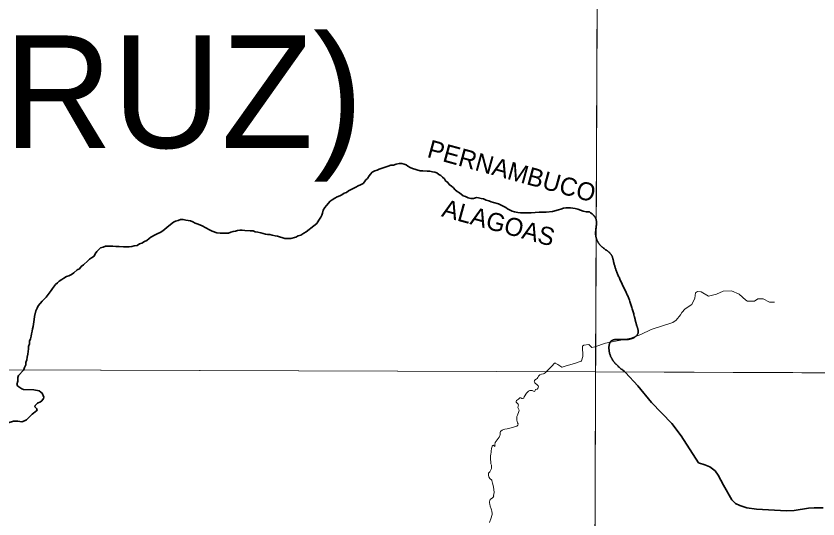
# Model space of a CAD drawing. Extents: x -1643653 to 4543381, y 1624270 to 13878484.
# Drawn here: x 594066 to 597627, y 8920336 to 8922571 of the extents above; entities that cross this region are included whole.
import ezdxf
from ezdxf.enums import TextEntityAlignment as Align

# ---------------------------------------------------------------- set-up
doc = ezdxf.new("R2010")
doc.units = 0
doc.header["$LTSCALE"] = 200
doc.linetypes.add('LONG_DASH_SHORT_DASH', pattern=[9.9, 6, -1.2, 1.5, -1.2])
doc.layers.add('6', color=7, linetype='Continuous', lineweight=13)
doc.layers.add('60', color=7, linetype='Continuous', lineweight=13)

msp = doc.modelspace()

# ---------------------------------------------------------------- linework, layer by layer
at = {"layer": '6'}
for points in [[(585656.3, 8924738.8), (596655.5, 8924715.8), (596639.8, 8920989.8), (585645.8, 8921027.3)], [(607600.8, 8920952.4), (596639.8, 8920989.8), (596608.8, 8909934.4), (607569.8, 8909894.9)]]:
    msp.add_lwpolyline(points, close=True, dxfattribs=at)
for points in [[(596655.5, 8924715.8), (596593.3, 8909930.3), (596531.7, 8896026.7)], [(597434.3, 8921299.7), (597411.5, 8921299.7), (597383.8, 8921313.7), (597360.5, 8921314.5), (597345.6, 8921303.6), (597314.4, 8921304.1), (597306.5, 8921308), (597277.6, 8921334.7), (597243.3, 8921349.7), (597206.9, 8921347.9), (597176.8, 8921335.1), (597140.6, 8921326.9), (597109.4, 8921345.3), (597091.8, 8921347), (597084, 8921340.9), (597080.4, 8921317.9), (597067.7, 8921289.1), (597038.2, 8921270.1), (597022.5, 8921254), (597017.6, 8921243.4), (596998.4, 8921219.3), (596982.5, 8921209.2), (596886.2, 8921177.5), (596841.4, 8921155.3), (596796, 8921139.4), (596684.4, 8921117.9), (596636.5, 8921101.1), (596623.7, 8921097.9), (596609.9, 8921111.7), (596587.7, 8921108.9), (596581.2, 8921103.5)], [(596581.2, 8921103.5), (596583.4, 8921058), (596577.4, 8921038.4), (596576.5, 8921036.9), (596546.9, 8921026.8), (596509.1, 8921016.7), (596491.7, 8921010.3), (596490, 8921010.8), (596472.1, 8921022.3), (596460.7, 8921029.2), (596459.6, 8921029.6), (596457.7, 8921028), (596445.2, 8921015.4), (596419.5, 8920988.9)], [(574684.9, 8921064.7), (596639.8, 8920989.8), (607636.3, 8920937.2), (626625.7, 8920820.5)], [(596419.5, 8920988.9), (596416.1, 8920985.5), (596411.6, 8920983.1), (596407.8, 8920981.7), (596399.5, 8920980), (596392.7, 8920976.5), (596389.8, 8920974.2), (596389.4, 8920973.2), (596388.5, 8920972.8), (596388, 8920971.8), (596387, 8920970.8), (596385.5, 8920968), (596383.2, 8920964.5), (596380.2, 8920960.7), (596376.2, 8920958.1), (596372.5, 8920956.2), (596369.6, 8920953.6), (596368.4, 8920952), (596367.4, 8920948.3), (596368.1, 8920946.1), (596368.2, 8920944.4), (596370, 8920941.5), (596371.9, 8920939.1), (596374.2, 8920937.3), (596377.3, 8920934.5), (596381, 8920931.9), (596384.8, 8920927.5), (596384.8, 8920927.5), (596385.6, 8920924.6), (596383.9, 8920916.4), (596383.6, 8920915.6), (596379.7, 8920913.5), (596373.2, 8920911.8), (596371.3, 8920906.5), (596370.2, 8920904.4), (596367.6, 8920903.1), (596364.1, 8920903.5), (596358.3, 8920907.2), (596357.3, 8920907.5), (596352.8, 8920907.7), (596347.5, 8920907.1), (596342.6, 8920904.7), (596337.1, 8920900), (596333.1, 8920895.9), (596322.9, 8920878.2)], [(596322.9, 8920878.2), (596321.8, 8920875.5), (596320.5, 8920873.2), (596315.8, 8920871.4), (596312.6, 8920871.3), (596310.4, 8920872.7), (596308.4, 8920874.5), (596303, 8920874.9), (596298.1, 8920868.6), (596293.7, 8920866.1), (596288.5, 8920862.6), (596287.3, 8920858.1), (596287.3, 8920855.8), (596289.2, 8920853.1), (596295.7, 8920846.8), (596296.2, 8920845.8), (596296.8, 8920842.9), (596295, 8920832), (596300.2, 8920819.4), (596299.3, 8920813.8), (596292.4, 8920797.3), (596290.7, 8920791.7), (596289.4, 8920786.3), (596290.7, 8920775), (596292.3, 8920769.4), (596293.4, 8920763.9), (596295.3, 8920758.3), (596294.3, 8920752.9), (596293.5, 8920751), (596289.7, 8920748.2), (596275.6, 8920744), (596269.9, 8920743.1), (596264.5, 8920741.9), (596258.8, 8920739.7), (596253.2, 8920738.4), (596247.6, 8920736.7), (596236.5, 8920735.2), (596230.9, 8920733.7), (596225.4, 8920731.3), (596218.8, 8920726.5), (596218.2, 8920725.5), (596216.7, 8920722.2), (596215.8, 8920715.7), (596215.7, 8920710.1), (596215.3, 8920707.1), (596211.6, 8920699.2), (596197.7, 8920682), (596193.8, 8920675.4), (596193.1, 8920667.7), (596194.2, 8920664.1), (596192.8, 8920660.7), (596192.2, 8920658.1), (596192, 8920658), (596185.8, 8920663.5), (596183.3, 8920663.3), (596181.1, 8920659.8), (596179.3, 8920654.3), (596178.1, 8920648.7), (596176.8, 8920637.8), (596175.7, 8920632), (596175.2, 8920626.1), (596173.4, 8920615.3), (596172.7, 8920609.8), (596172.8, 8920603.6), (596174.4, 8920586.9), (596175.3, 8920581.1), (596177.2, 8920575.1), (596177.8, 8920569.5), (596177.6, 8920563.3), (596177.3, 8920560), (596173.2, 8920551.4), (596169.7, 8920546), (596164.5, 8920539), (596163.8, 8920534.7), (596164.4, 8920529.3), (596165.8, 8920523.5), (596169.8, 8920515.6), (596179, 8920508.3), (596179.7, 8920507.3), (596181.2, 8920501.9), (596182.2, 8920495.7), (596184.6, 8920484.3), (596186.5, 8920477.5), (596189.9, 8920455.4)], [(596189.9, 8920455.4), (596189.5, 8920454.3), (596187.2, 8920440.2), (596187.2, 8920439.4), (596188.3, 8920437.7), (596188.3, 8920437.1), (596185.5, 8920433.8), (596181.5, 8920430.2), (596172.4, 8920423), (596169.5, 8920418.8), (596168.2, 8920412.8), (596168.7, 8920407.7), (596169.5, 8920402.7), (596172, 8920392.7), (596176.5, 8920381.4), (596178, 8920376.9), (596179.2, 8920371.6), (596180.6, 8920361.1), (596180.6, 8920356.3), (596179.6, 8920351.4), (596176.7, 8920340.8), (596168, 8920320.1)]]:
    msp.add_lwpolyline(points, dxfattribs=at)
at = {"layer": '6', "linetype": 'LONG_DASH_SHORT_DASH', "lineweight": 35}
for points in [[(595503.7, 8921771.9), (595513.3, 8921776.4), (595523.8, 8921783.5), (595533.3, 8921787.6), (595542.8, 8921794.6), (595554.8, 8921799.7), (595565.9, 8921806.8), (595575.4, 8921810.3), (595584.9, 8921816.9), (595595.4, 8921821), (595607, 8921827), (595613.5, 8921834.6), (595619.5, 8921842.7), (595626.5, 8921849.7), (595635, 8921860.3), (595640.5, 8921868.3), (595647.9, 8921877.9), (595660, 8921882.5), (595669.5, 8921886.5), (595678, 8921891.1), (595709.1, 8921900.8), (595718.1, 8921904.3), (595730.2, 8921907.9), (595742.2, 8921908.9), (595753.8, 8921913), (595767.3, 8921916.1), (595779.9, 8921915.6), (595789.4, 8921912.7), (595799, 8921909.2), (595806.5, 8921903.2), (595816.6, 8921897.7), (595827.1, 8921893.8), (595861.3, 8921882.9), (595871.9, 8921882.9), (595892.5, 8921882), (595904, 8921881.1), (595916.1, 8921878.1), (595925.6, 8921877.1), (595934.7, 8921873.7), (595943.7, 8921867.2), (595952.3, 8921861.7), (595960.3, 8921855.2), (595968.4, 8921847.7), (595974, 8921838.7), (595983.5, 8921831.2), (595990.1, 8921821.7), (596000.2, 8921815.7), (596007.7, 8921809.2), (596016.8, 8921798.7), (596024.9, 8921790.7), (596035.4, 8921784.8), (596052.1, 8921771.8), (596061.6, 8921768.8), (596073.7, 8921763.3), (596085.2, 8921760.4), (596097.3, 8921760.4), (596110.3, 8921764.5), (596119.9, 8921763.6), (596131.4, 8921760.1), (596142.5, 8921759.1), (596153.6, 8921753.2), (596165.6, 8921749.7), (596176.7, 8921745.2), (596186.7, 8921741.8), (596208.8, 8921735.8), (596232, 8921724.4), (596241.6, 8921720.9), (596249.1, 8921714.9), (596268.7, 8921704.5), (596279.8, 8921701), (596294.3, 8921698.1), (596306.9, 8921697.1), (596320, 8921696.7), (596353.6, 8921696.8), (596389.2, 8921699), (596420.4, 8921700.1), (596448.5, 8921702.3), (596474.6, 8921709.4), (596486.1, 8921713.5), (596497.6, 8921717), (596508.2, 8921718.1), (596528.7, 8921718.2), (596538.8, 8921717.7), (596549.8, 8921716.3), (596560.4, 8921712.3), (596572.5, 8921708.8), (596585, 8921703.4), (596598.6, 8921701.4), (596611.6, 8921701.5)], [(594412.5, 8921504.4), (594417, 8921514), (594424.5, 8921525.1), (594441.5, 8921540.7), (594453.5, 8921543.8), (594464, 8921547.8), (594495.2, 8921548), (594509.2, 8921547.5), (594523.3, 8921547.6), (594543.9, 8921545.7), (594569, 8921545.8), (594580.6, 8921546.3), (594590.1, 8921549.9), (594603.7, 8921551.5), (594614.2, 8921558.1), (594625.2, 8921562.1), (594636.2, 8921569.7), (594646.8, 8921574.3), (594657.3, 8921581.8), (594664.3, 8921588.9), (594683.8, 8921599), (594696.4, 8921604.1), (594705.9, 8921609.2), (594718.4, 8921616.8), (594744.4, 8921639), (594765, 8921654.6), (594774, 8921659.2), (594786.5, 8921662.7), (594796.6, 8921666.8), (594808.1, 8921666.8), (594820.7, 8921664.4), (594841.3, 8921661.5), (594851.3, 8921657), (594860.9, 8921651), (594870.5, 8921647.1), (594883, 8921642.6), (594893.1, 8921638.6), (594925.8, 8921621.2), (594936.4, 8921614.7), (594958, 8921608.3), (594972.1, 8921605.8), (594986.1, 8921605.9), (594998.2, 8921606.4), (595010.2, 8921606.5), (595019.3, 8921610.1), (595029.8, 8921613.6), (595040.8, 8921614.7), (595049.9, 8921618.2), (595059.9, 8921618.8), (595070, 8921618.8), (595081.5, 8921618.4), (595106.1, 8921616.5), (595118.7, 8921616), (595128.2, 8921612.6), (595140.3, 8921610.1), (595153.9, 8921608.2), (595162.9, 8921604.7), (595173.5, 8921601.7), (595183, 8921600.8), (595193.1, 8921600.3), (595203.6, 8921596.8), (595217.2, 8921593.9), (595226.7, 8921592.9), (595259.9, 8921582), (595287, 8921582.1), (595309.1, 8921588.3), (595319.1, 8921594.3), (595331.2, 8921597.9), (595343.7, 8921605.5), (595354.2, 8921612.6), (595388.8, 8921638.3), (595402.3, 8921649.4), (595410.8, 8921664.5), (595419.2, 8921676.6), (595423.7, 8921686.2), (595427.2, 8921695.2), (595430.2, 8921707.8), (595437.2, 8921719.8), (595444.2, 8921729.4), (595460.7, 8921748.6), (595469.7, 8921754.1), (595481.2, 8921762.2), (595491.7, 8921767.8), (595503.7, 8921771.9)], [(594099.8, 8920996.9), (594100.5, 8921000.4), (594104, 8921009.5), (594109.4, 8921021.6), (594109.9, 8921032.1), (594113.9, 8921042.7), (594114.8, 8921055.2), (594118.3, 8921067.8), (594119.8, 8921079.9), (594121.7, 8921092.4), (594121.7, 8921102.5), (594125.7, 8921114.5), (594126.1, 8921125.6), (594130.1, 8921136.6), (594133.6, 8921148.2), (594134.5, 8921159.3), (594138, 8921170.8), (594138.5, 8921180.4), (594142.4, 8921191.4), (594146.8, 8921222.6), (594147.8, 8921236.1), (594153.7, 8921261.3), (594160.2, 8921273.3), (594164.2, 8921283.4), (594181.7, 8921304.6), (594199.2, 8921321.7), (594213.7, 8921339.4), (594222.2, 8921350.9), (594228.2, 8921360.5), (594241.7, 8921377.7), (594249.7, 8921386.2), (594257.7, 8921393.3), (594269.2, 8921400.9), (594278.7, 8921405.9), (594289.8, 8921413), (594300.8, 8921417.1), (594311.8, 8921422.1), (594322.3, 8921429.7), (594337.9, 8921443.3), (594348.4, 8921448.4), (594354.9, 8921457.5), (594365.9, 8921466.1), (594384.9, 8921482.7), (594392.4, 8921491.3), (594401.5, 8921496.3), (594412.5, 8921504.4)], [(594176.2, 8920899.4), (594168.7, 8920905.5), (594145.6, 8920910), (594098.9, 8920911.9), (594091.7, 8920913.9), (594073.9, 8920925.8), (594070.1, 8920934.3), (594074.3, 8920949.1), (594073.3, 8920964.4), (594077, 8920974.4), (594099.8, 8920996.9)], [(596772.7, 8920987.6), (596827.2, 8920927.7), (596887.6, 8920854.4), (596978.3, 8920759.7), (597020.1, 8920705.3), (597096.6, 8920585), (597125.2, 8920577.1), (597146.5, 8920568.5), (597170.2, 8920550.2), (597184.9, 8920530.7), (597208.4, 8920486.7), (597244.6, 8920421.2), (597260.6, 8920405.6), (597280.5, 8920395.7), (597310.8, 8920386.4), (597353.9, 8920380.3), (597487.5, 8920372), (597521, 8920374.3), (597585, 8920384.1), (597610.2, 8920386.4), (597650.2, 8920385.4)], [(594030.9, 8920764), (594054.9, 8920770.3), (594073.9, 8920770.6), (594092, 8920768.1), (594103, 8920771.6), (594111.8, 8920776.3), (594138.2, 8920802.2), (594156.9, 8920817.3), (594159.3, 8920821.2), (594159, 8920825), (594150, 8920833.8), (594150.8, 8920840.9), (594161, 8920850.4), (594174.3, 8920856.6), (594180.7, 8920861.6), (594187.3, 8920871.1), (594189.3, 8920877.9), (594182.3, 8920894.6), (594176.2, 8920899.4)]]:
    msp.add_lwpolyline(points, dxfattribs=at)
msp.add_spline([(596611.2, 8921701.9), (596639.9, 8921673.2), (596639.9, 8921601.6), (596665.6, 8921547.2), (596711.4, 8921507.1), (596720, 8921478.5), (596734.3, 8921432.6), (596788.7, 8921312.3), (596811.6, 8921237.9), (596823.1, 8921194.9), (596828.8, 8921163.4), (596788.7, 8921134.8), (596705.7, 8921123.3), (596700, 8921083.2), (596772.7, 8920987.6)], degree=3, dxfattribs=at)
at = {"layer": '60', "lineweight": 25}
msp.add_spline([(814781, 9009175.5), (814787.2, 9009173.4), (814796.9, 9009173.4), (814799.4, 9009172.4), (814805.1, 9009174.5), (814805.6, 9009176.5), (814811.7, 9009179.5), (814811.7, 9009179.5), (814801.5, 9009181), (814790.7, 9009181.5), (814784.1, 9009183.1), (814777.4, 9009185.1), (814778.4, 9009175.5)], degree=3, dxfattribs=at)

# ---------------------------------------------------------------- texts
at = {"layer": '6'}
msp.add_text('(POÇO DA CRUZ)', height=500, dxfattribs=at).set_placement((590036.9, 8921984.9))
for s, p in [('PERNAMBUCO', (596257.1, 8921844)), ('ALAGOAS', (596198.5, 8921614.1))]:
    msp.add_text(s, height=80, rotation=344.671, dxfattribs=at).set_placement(p, align=Align.CENTER)

doc.saveas('drawing.dxf')
